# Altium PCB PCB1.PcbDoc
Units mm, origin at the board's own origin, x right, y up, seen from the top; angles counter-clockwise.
Board outline 84.71 x 55.88 mm, 2 copper layers (Top Layer, Bottom Layer); 58 components, 56 nets, 256 pads, 84 vias.
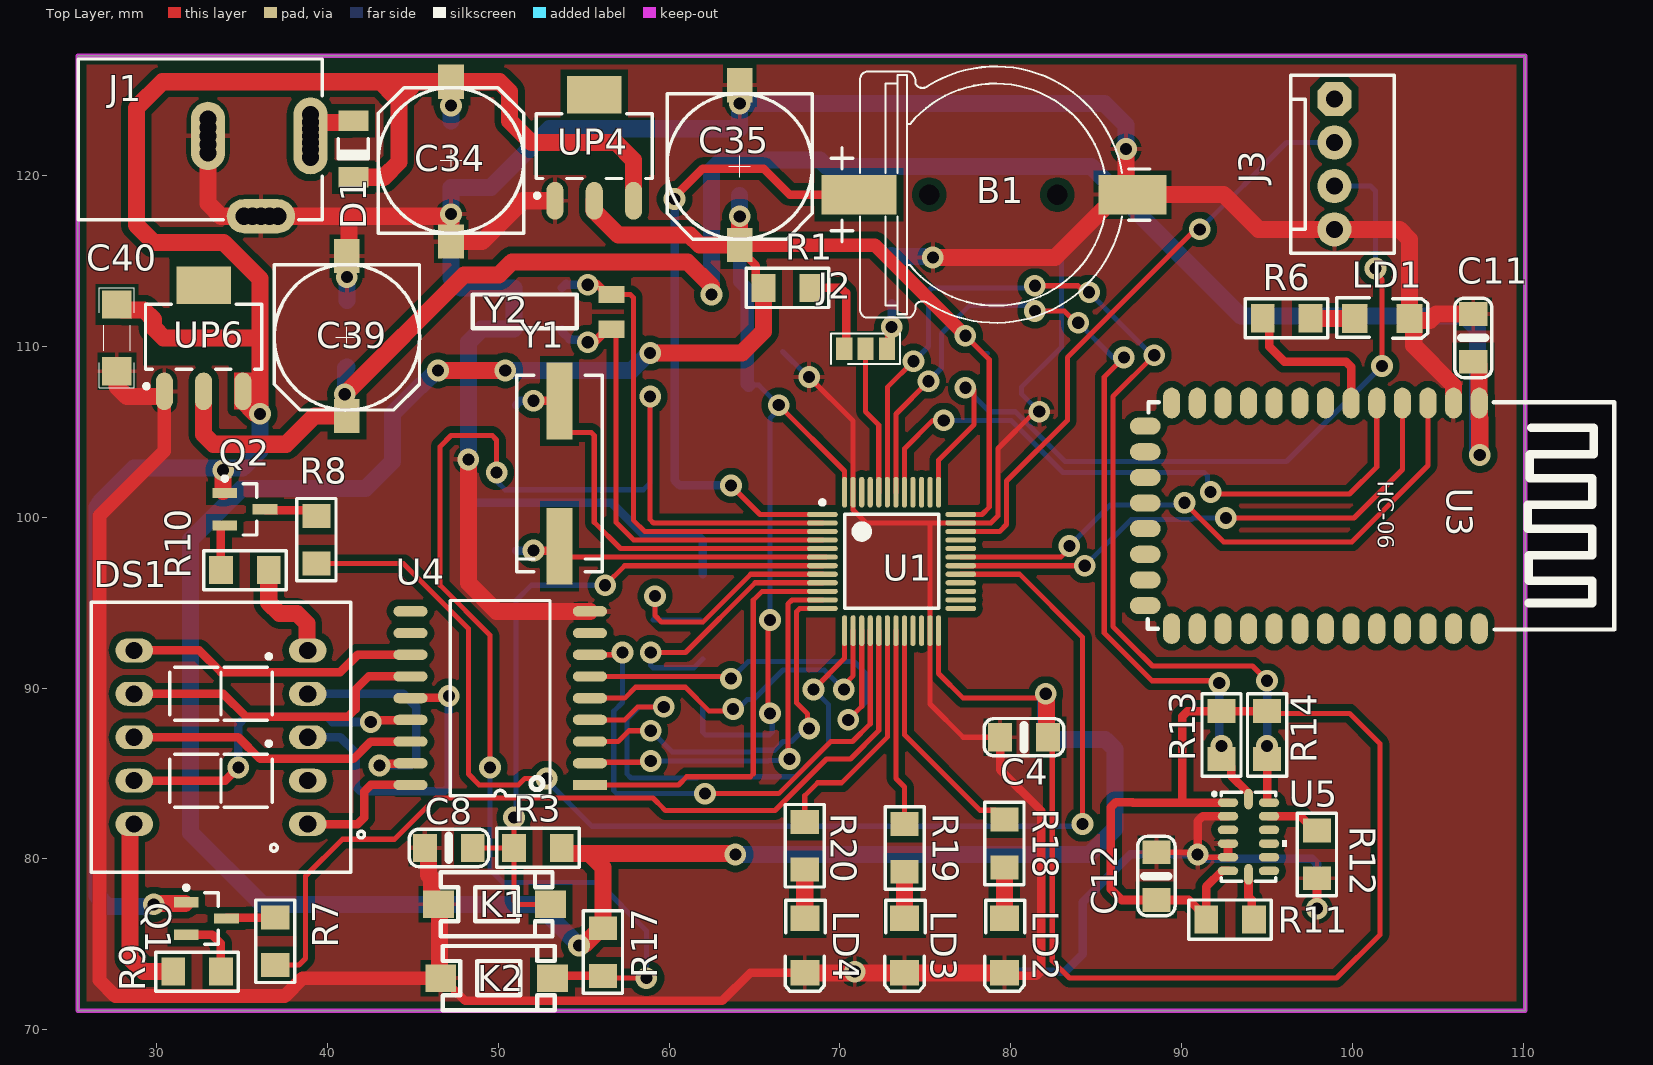
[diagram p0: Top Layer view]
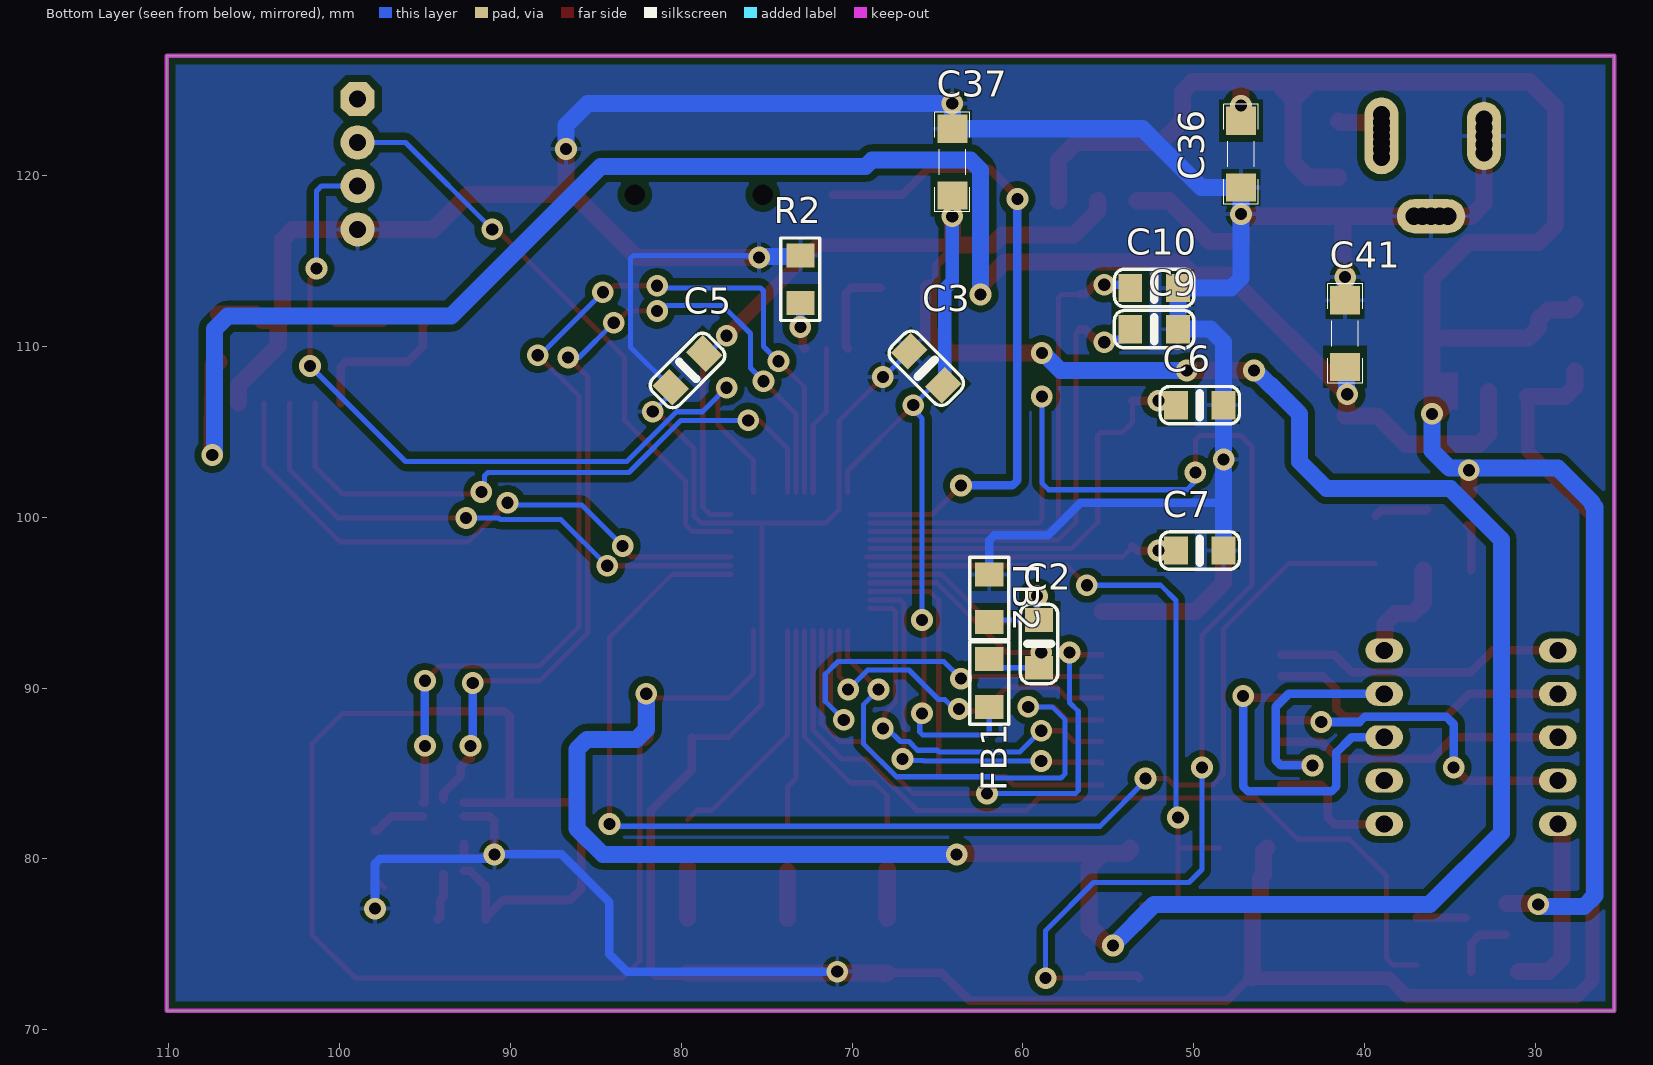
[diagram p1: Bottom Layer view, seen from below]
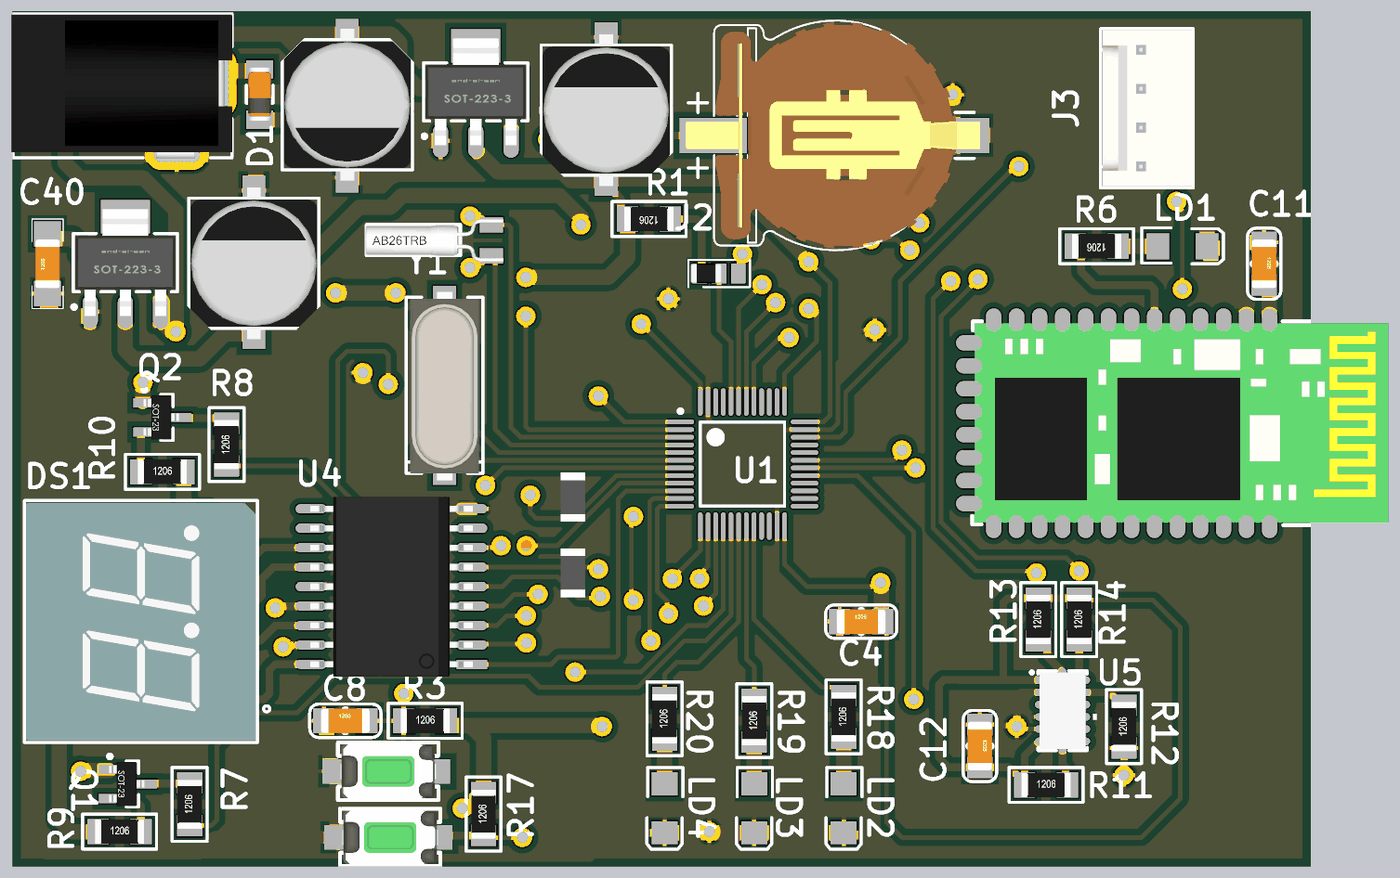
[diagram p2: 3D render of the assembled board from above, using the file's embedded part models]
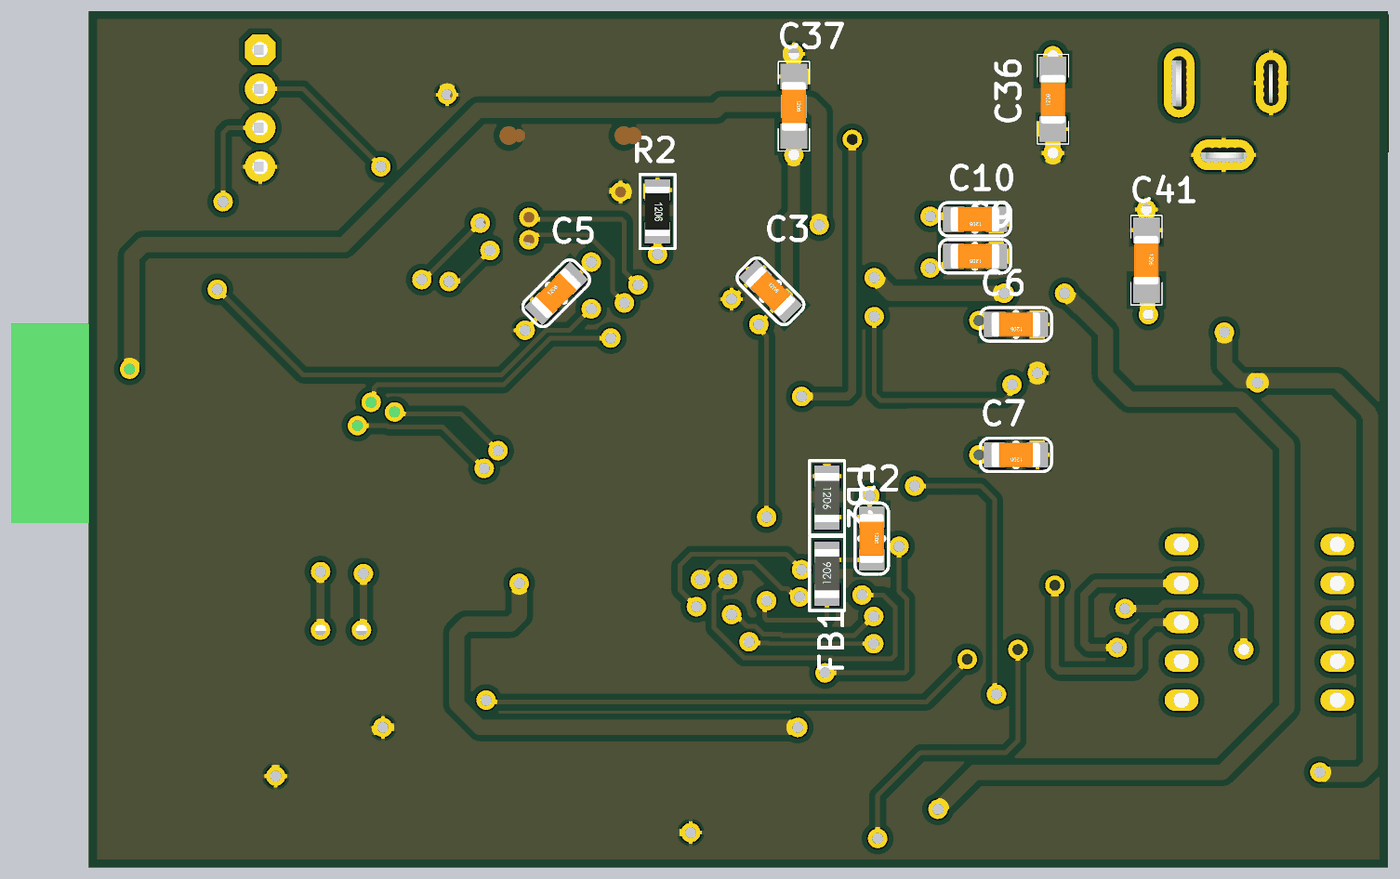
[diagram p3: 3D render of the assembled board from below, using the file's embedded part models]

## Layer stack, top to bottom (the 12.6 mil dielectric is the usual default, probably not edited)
Top Solder: solder mask 0.0102, Solder Resist, Dk 3.5
Top Layer: signal copper 0.0356
Dielectric 1: dielectric 0.32, FR-4, Dk 4.8
Bottom Layer: signal copper 0.0356
Bottom Solder: solder mask 0.0102, Solder Resist, Dk 3.5

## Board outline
25.4,71.12 110.109,71.12 110.109,127 25.4,127

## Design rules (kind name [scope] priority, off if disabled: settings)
Clearance [All] p1: gap=0.4 ignorepadtopadclearanceinfootprint=FALSE
PolygonConnect [All] p1: connectstyle=Relief reliefconductorwidth=0.254 reliefentries=4 polygonreliefangle="90 Angle" airgapwidth=0.254
RoutingVias [All] p1: holewidth=0.711 width=1.27 viastyle="Through Hole" minholewidth=0.711 minwidth=1.27 maxholewidth=0.711 maxwidth=1.27
SolderMaskExpansion [All] p1: expansion=0.102 istentingtop=FALSE
Width [All] p1: maxlimit=1 minlimit=0.254 preferedwidth=0.4
30 further rules are at their usual default settings.

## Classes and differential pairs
component class Segment: DS1 Q1 Q2 R7 R8 R9 R10 U4
component class PowerSupply: C34 C35 C36 C37 C39 C40 C41 D1 J1 UP4 UP6
component class Microcontroller: B1 C2 C3 C4 C5 C6 C7 C8 C9 C10 FB1 FB2 J2 J3 K1 K2 LD2 LD3 LD4 R1 R2 R3 R17 R18 R19 R20 U1 Y1 Y2
component class HC05: C11 LD1 R6 U3
component class ADXL345: C12 R11 R12 R13 R14 U5

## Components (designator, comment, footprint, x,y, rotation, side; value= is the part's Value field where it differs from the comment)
B1 "Battery" "Battery socket SMD" 79.121,118.872 r180 top
C2 "Capacitor SMD" "1206 Capacitor" 59.055,92.583 r270 bottom
C3 "Capacitor SMD" "1206 Capacitor" 65.659,108.712 r225 bottom
C4 "Capacitor SMD" "1206 Capacitor" 80.772,87.122 r0 top
C5 "Capacitor SMD" "1206 Capacitor" 79.629,108.585 r135 bottom
C6 "Capacitor SMD" "1206 Capacitor" 49.657,106.553 r0 bottom
C7 "Capacitor SMD" "1206 Capacitor" 49.657,98.044 r0 bottom
C8 "Capacitor SMD" "1206 Capacitor" 47.117,80.645 r0 top
C9 "Capacitor SMD" "1206 Capacitor" 52.324,110.998 r0 bottom
C10 "Capacitor SMD" "1206 Capacitor" 52.324,113.411 r0 bottom
C11 "Capacitor SMD" "1206 Capacitor" 107.061,110.49 r270 top
C12 "Capacitor SMD" "1206 Capacitor" 88.519,78.994 r270 top
C34 "" "CAPACITOR RADIAL SMT size F" 47.244,120.873 r90 top
C35 "" "CAPACITOR RADIAL SMT size F" 64.135,120.523 r270 top
C36 "0.1uF" CAPC4817X12N 47.244,121.24 r90 bottom
C37 "0.1uF" CAPC4817X12N 64.135,120.777 r270 bottom
C39 "" "CAPACITOR RADIAL SMT size F" 41.148,110.521 r270 top
C40 "0.1uF" CAPC4817X12N 27.686,110.49 r90 top
C41 "0.1uF" CAPC4817X12N 41.148,110.744 r270 bottom
D1 "1N4148" "Diode 1n4148 SMD" 41.529,123.188 r270 top
DS1 "7SEG_2DIGIT_CA" 7SEGX2_10_03INCH 33.782,87.122 r90 top
FB1 "Ferrit Bead" "1206 Ferrit Bead" 61.976,90.297 r90 bottom
FB2 "Ferrit Bead" "1206 Ferrit Bead" 61.976,95.25 r270 bottom
J1 "DC Power Jack" "DC Power Jack 1" 39.02,123.109 r0 top
J2 "Jumper Selector 3x1" "Jumper Selector 3x1 SMT" 71.501,109.855 r0 top
J3 "SWD" "CON WF_4" 98.933,120.65 r270 top
K1 "Push Kay" "Push Kay 4 KFC" 49.911,77.343 r270 top
K2 "Push Kay" "Push Kay 4 KFC" 50.038,73.025 r270 top
LD1 "SMD LED" "LED_1206 RED" 101.727,111.633 r0 top
LD2 "SMD LED" "LED_1206 RED" 79.629,74.93 r270 top
LD3 "SMD LED" "LED_1206 RED" 73.787,74.93 r270 top
LD4 "SMD LED" "LED_1206 RED" 67.945,74.93 r270 top
Q1 "BC807" SOT-23 32.925,76.515 r270 top
Q2 "BC807" SOT-23 35.179,100.457 r270 top
R1 "Resistor SMD" "1206 Resistor" 66.929,113.411 r180 top
R2 "Resistor SMD" "1206 Resistor" 73.025,113.919 r270 bottom
R3 "Resistor SMD" "1206 Resistor" 52.324,80.645 r0 top
R6 "Resistor SMD" "1206 Resistor" 96.139,111.633 r180 top
R7 "Resistor SMD" "1206 Resistor" 36.957,75.184 r90 top
R8 "Resistor SMD" "1206 Resistor" 39.37,98.679 r90 top
R9 "Resistor SMD" "1206 Resistor" 32.385,73.406 r0 top
R10 "Resistor SMD" "1206 Resistor" 35.179,96.901 r0 top
R11 "Resistor SMD" "1206 Resistor" 92.837,76.454 r0 top
R12 "Resistor SMD" "1206 Resistor" 97.917,80.264 r90 top
R13 "Resistor SMD" "1206 Resistor" 92.329,87.249 r90 top
R14 "Resistor SMD" "1206 Resistor" 94.996,87.249 r90 top
R17 "Resistor SMD" "1206 Resistor" 56.134,74.549 r90 top
R18 "Resistor SMD" "1206 Resistor" 79.629,80.899 r90 top
R19 "Resistor SMD" "1206 Resistor" 73.787,80.645 r90 top
R20 "Resistor SMD" "1206 Resistor" 67.945,80.772 r90 top
U1 "STM32F103C8T6" STM-LQFP48_N 73.025,97.409 r0 top
U3 "HC-05" BT_HC06 97.663,100.076 r270 top
U4 "ULN2803" SOIC18 50.122,89.408 r180 top
U5 "ADXL345" QFN80_14_5X3 93.91,81.299 r0 top
UP4 "LM1117IMP-3.3" SOT223_4 55.626,121.714 r90 top
UP6 "LM1117IMP-3.3" SOT223_4 32.766,110.562 r90 top
Y1 "Xtal" "Crystal SMD" 53.594,101.981 r90 top
Y2 "Xtal" "Xtal 32.782khz" 56.642,112.014 r180 top

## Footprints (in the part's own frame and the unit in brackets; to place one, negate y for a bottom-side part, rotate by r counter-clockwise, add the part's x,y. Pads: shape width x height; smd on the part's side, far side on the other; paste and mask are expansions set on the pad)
7SEGX2_10_03INCH [mm] "7SEG 2DIGIT 10pin Pitch: 2.54mm  0.3\", 15.5X15mm"
  oval 1.4x2.2 hole 1: 1(-5.08,-5.08) 3(0,-5.08) 4(2.54,-5.08) 5(5.08,-5.08) 6(5.08,5.08) 7(2.54,5.08) 8(0,5.08) 9(-2.54,5.08) 10(-5.08,5.08) ""(-2.54,-5.08)
  silkscreen extent -7.9,-8.4 7.9,7.6, body extent -7.75,-7.5 7.75,7.5, height 7.3
"1206 Capacitor" [mil]
  rect 55x65 smd: 1(-55,0) 2(55,0)
  silkscreen extent -92,-43 92,43, body extent -63,-31 63,31, height 39
"1206 Ferrit Bead" [mil]
  rect 55x65 smd: 1(-55,0) 2(55,0)
  silkscreen extent -95,-45 95,45, body extent -63,-31 63,31, height 26
"1206 Resistor" [mil]
  rect 55x65 smd: 1(-55,0) 2(55,0)
  silkscreen extent -95,-45 95,45, body extent -63,-31 63,31, height 24
"Battery socket SMD" [mm]
  rect 4.4x2.3 smd mask+0.05: 1(8,0)
  rect 4x2.3 smd mask+0.05: 2(-8,0)
  round 0.5 hole 1.2 unplated mask+0.05: ""(-3.6,0) ""(3.9,0)
  silkscreen extent -9.02,-7.5 9.63,7.5, body extent -9.4,-7.37 9.8,7.37, height 4.25
BT_HC06 [mm] "Bluetooth HC-06"
  oval 1.8x1 smd: 1(-6.6,9.75) 2(-6.6,8.25) 3(-6.6,6.75) 4(-6.6,5.25) 5(-6.6,3.75) 6(-6.6,2.25) 7(-6.6,0.75) 8(-6.6,-0.75) 9(-6.6,-2.25) 10(-6.6,-3.75) 11(-6.6,-5.25) 12(-6.6,-6.75) 13(-6.6,-8.25) 22(6.6,-8.25) 23(6.6,-6.75) 24(6.6,-5.25) 25(6.6,-3.75) 26(6.6,-2.25) 27(6.6,-0.75) 28(6.6,0.75) 29(6.6,2.25) 30(6.6,3.75) 31(6.6,5.25) 32(6.6,6.75) 33(6.6,8.25) 34(6.6,9.75)
  oval 1x1.8 smd: 14(-5.25,-9.8) 15(-3.75,-9.8) 16(-2.25,-9.8) 17(-0.75,-9.8) 18(0.75,-9.8) 19(2.25,-9.8) 20(3.75,-9.8) 21(5.25,-9.8)
  silkscreen extent -6.65,-9.65 6.65,17.65, body extent -6.5,-9.5 6.5,17.5, height 4.3
"CAPACITOR RADIAL SMT size F" [mm]
  rect 2x1.5 smd mask+0.051: 1(4.603,0) 2(-4.75,0)
  silkscreen extent -4.26,-4.26 4.26,4.25, body extent -4.95,-4.15 4.95,4.15, height 10.02
CAPC4817X12N [mm] "Chip Capacitor, 2-Leads, Body 4/80x1/70mm, IPC Medium Density-Design:Abbas Basereh"
  rect 1.65x1.75 smd: 1(-1.95,0) 2(1.95,0)
  silkscreen extent -2.92,-1.02 2.92,1.02, body extent -1.6,-0.8 1.6,0.8, height 1
"CON WF_4" [mm] "DS1070  WF, Cvilux CI31 pitch 2.54mm-Designer Abbas Basereh"
  oct 2x2 hole 1: 1(-3.81,0)
  round 2 hole 1: 2(-1.27,0) 3(1.27,0) 4(3.81,0)
  silkscreen extent -5.2,-2.55 5.2,3.5, body extent -5.08,-2.4 5.08,3.4, height 11.56
"Crystal SMD" [mm]
  rect 4.5x1.5 smd: 1(-3.683,0) 2(4.817,0)
  silkscreen extent -5.18,-2.5 6.32,2.5, body extent -5.64,-2.25 6.66,2.25, height 5.18
"DC Power Jack 1" [mm] "Power Adaptor Jack"
  round 1.5 hole 1: 1(0,-2.05) 1(0,-1.6) 1(0,-1.2) 1(0,-0.4) 1(0,0) 1(0,0.45) 2(-6,-1.8) 2(-6,0.2) 2(-6,-1.3) 2(-6,-0.3) 3(-3.9,-5.5) 3(-3.4,-5.5) 3(-2.4,-5.5) 3(-1.9,-5.5)
  oval 2x4.5 hole 1: 1(0,-0.8)
  oval 2x4 hole 1: 2(-6,-0.8)
  oval 4x2 hole 1: 3(-2.9,-5.5)
  silkscreen extent -13.59,-5.7 0.7,3.7, body extent -13.68,-5.74 0.72,3.66, height 11.05
"Diode 1n4148 SMD" [mm] "Mini MELF SOD-80"
  rect 1.2x1.75 smd: 1(0,0) 2(3.3,0)
  silkscreen extent 1.04,-0.88 2.22,0.87, body extent -0.13,-0.75 3.37,0.75, height 1.55
"Jumper Selector 3x1 SMT" [mm]
  rect 0.95x1.3 smd: 1(-1.25,0) 2(0,0) 3(1.25,0)
  silkscreen extent -2.01,-0.89 2.01,0.89, body extent -1.85,-0.63 0.18,0.64, height 0.6
"LED_1206 RED" [mm]
  rect 1.5x1.7 smd: 1(-1.6,0) 2(1.6,0)
  silkscreen extent -2.65,-1.15 2.67,1.2, body extent -1.6,-0.8 1.6,0.8, height 1.11
"Push Kay 4 KFC" [mm]
  rect 1.6x1.8 smd mask+0.04: 1(0,3.15) 2(0,-3.4)
  silkscreen extent -1.88,-3.27 1.87,3.28, body extent -1.75,-3.15 1.75,3.15, height 5.03
QFN80_14_5X3 [mm] "LGA_CC-14-1 ADXL345"
  oval 1.2x0.5 smd mask+0.075: 1(-1.2,2) 2(-1.2,1.2) 3(-1.2,0.4) 4(-1.2,-0.4) 5(-1.2,-1.2) 6(-1.2,-2) 8(1.2,-2) 9(1.2,-1.2) 10(1.2,-0.4) 11(1.2,0.4) 12(1.2,1.2) 13(1.2,2)
  oval 0.5x1.2 smd mask+0.075: 7(0,-2.2) 14(0,2.2)
  silkscreen extent -2.1,-2.6 2.24,2.6, body extent -1.5,-2.5 1.5,2.5, height 1.03
SOIC18 [mm]
  rect 2x0.6 smd: 1(-5.25,5.08)
  oval 2x0.6 smd: 2(-5.25,3.81) 3(-5.25,2.54) 4(-5.25,1.27) 5(-5.25,0) 6(-5.25,-1.27) 7(-5.25,-2.54) 8(-5.25,-3.81) 9(-5.25,-5.08) 10(5.25,-5.08) 11(5.25,-3.81) 12(5.25,-2.54) 13(5.25,-1.27) 14(5.25,0) 15(5.25,1.27) 16(5.25,2.54) 17(5.25,3.81) 18(5.25,5.08)
  silkscreen extent -2.91,-5.71 2.92,5.71, body extent -5.3,-5.87 5.3,5.88, height 2.67
SOT223_4 [mm] "SOT223, 4-Leads, Body 6.5x3.5mm, Pitch 2.30mm-Designer Abbas Basereh"
  oval 2.2x1 smd: 1(-3.2,2.3) 2(-3.2,0) 3(-3.2,-2.3)
  rect 2.2x3.2 smd: 4(3,0)
  Top Layer pour cut-out: -1.7,3.556 1.7,3.556 1.7,-3.556 -1.7,-3.556
  silkscreen extent -3.02,-3.4 1.9,3.47, body extent -3.5,-3.25 3.5,3.25, height 1.7
SOT-23 [mm]
  rect 0.6x1.45 smd: 1(-0.95,-1.175) 2(0.95,-1.175) 3(0,1.175)
  silkscreen extent -1.92,-1.3 1.5,0.7, body extent -1.45,-1.23 1.45,1.07, height 1
STM-LQFP48_N [mm] "QFP, 48-Leads, Body 7x7mm, Pitch 0.5mm, IPC Medium Density"
  oval 1.8x0.3 smd: 1(-4.05,2.75) 2(-4.05,2.25) 3(-4.05,1.75) 4(-4.05,1.25) 5(-4.05,0.75) 6(-4.05,0.25) 7(-4.05,-0.25) 8(-4.05,-0.75) 9(-4.05,-1.25) 10(-4.05,-1.75) 11(-4.05,-2.25) 12(-4.05,-2.75) 25(4.05,-2.75) 26(4.05,-2.25) 27(4.05,-1.75) 28(4.05,-1.25) 29(4.05,-0.75) 30(4.05,-0.25) 31(4.05,0.25) 32(4.05,0.75) 33(4.05,1.25) 34(4.05,1.75) 35(4.05,2.25) 36(4.05,2.75)
  oval 0.3x1.8 smd: 13(-2.75,-4.05) 14(-2.25,-4.05) 15(-1.75,-4.05) 16(-1.25,-4.05) 17(-0.75,-4.05) 18(-0.25,-4.05) 19(0.25,-4.05) 20(0.75,-4.05) 21(1.25,-4.05) 22(1.75,-4.05) 23(2.25,-4.05) 24(2.75,-4.05) 37(2.75,4.05) 38(2.25,4.05) 39(1.75,4.05) 40(1.25,4.05) 41(0.75,4.05) 42(0.25,4.05) 43(-0.25,4.05) 44(-0.75,4.05) 45(-1.25,4.05) 46(-1.75,4.05) 47(-2.25,4.05) 48(-2.75,4.05)
  silkscreen extent -4.17,-2.75 2.75,3.57, body extent -3.5,-3.5 3.5,3.5, height 1.6
"Xtal 32.782khz" [mil]
  rect 60x40 smd: 1(0,-40) 2(0,40)
  silkscreen extent 80,-40 320,38, body extent -31,-55 323,55, height 79

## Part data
B1: library part "Battry Backup"
C34 C35 C39: library part "Capacitor Tantalium"
C36 C37 C40 C41: library part "CAP SMD 1206", "CAP 1206"
D1: library part "1N4148 SMD", "General Semicoductor"
DS1: library part 7SEG_2DIGIT_CA_GRN_0.3INCH_10, "7SEGMENT, 2DIGIT, common cathode"
J1: "DC Power Jack. Center Pin 2.5mm. Diameter: 5.7mm"
J3: library part "Header 4 PIN Telecom.", "Header, 4-Pin Telecom."
LD1 LD2 LD3 LD4: library part "LED SMD"
U1: "ARM Cortex-M3 32-bit MCU, 64 KB Flash, 20 KB Internal RAM, 37 I/Os, 48-pin LQFP, -40 to 85 degC, Tray", I/Os (High Current)=37, Operating Frequency(F) (Processor speed) (MHz)=72, Supplier Part Number 1=497-6063-ND, Supply Voltage(Vcc) min (V)=2
U3: library part BT_HC-05_HDR, "Bluetooth Module, 2Mbps, 8Mb flash, 3.1~4.2V"
U5: library part ADXL345_LGA14, "Sensor, Accelerometer Digital, 3-Axis"
UP4 UP6: library part LM1117IMP-x.x, "x.x Volt, 800mA Low-Dropout Linear Regulator, 4-pin SOT-223"

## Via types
v1: diameter 1.27, hole 0.711, Top Layer to Bottom Layer, 84 vias

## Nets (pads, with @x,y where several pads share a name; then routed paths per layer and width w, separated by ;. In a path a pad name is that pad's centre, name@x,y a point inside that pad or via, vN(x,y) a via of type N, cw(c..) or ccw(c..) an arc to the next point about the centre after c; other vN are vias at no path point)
A: U1.10 U4.1 | length 24.2
  Top Layer w0.3: U4.1 60.56,84.328 61.036,84.805 64.752,84.805 64.928,84.981 64.928,95.133 65.454,95.659 U1.10
AGND: C2.1 FB2.2 U1.8 | length 16.7
  Top Layer w0.3: v1(59.182,95.377) 59.182,94.488 59.179,94.485 59.179,94.237 59.563,93.853 61.976,93.853 64.782,96.659 U1.8
  Bottom Layer w0.3: v1(59.182,95.377) 59.182,94.107 C2.1 61.849,93.98 FB2.2
B: U1.11 U4.2 | length 23
  Top Layer w0.3: U4.2 55.429,85.655 58.858,85.655 v1(58.928,85.725) ; v1(67.056,85.852) 66.968,85.94 66.968,94.926 67.201,95.159 U1.11
  Bottom Layer w0.3: v1(58.928,85.725) 65.778,85.725 65.821,85.768 66.972,85.768 v1(67.056,85.852)
BL_Key: U1.41 U3.5 | length 37.5
  Top Layer w0.3: U1.41 73.775,104.001 75.438,105.664 v1(76.073,105.664) ; v1(91.694,101.473) 91.821,101.346 99.822,101.346 101.413,102.937 U3.5
  Bottom Layer w0.3: v1(76.073,105.664) 80.01,105.664 83.058,102.616 91.313,102.616 91.508,102.421 91.508,101.659 v1(91.694,101.473)
BOOT0: J2.2 U1.44 | length 8.7
  Top Layer w0.3: J2.2 71.501,106.172 72.275,105.398 U1.44
C: U1.12 U4.3 | length 22.9
  Top Layer w0.3: U4.3 57.023,86.868 57.658,87.503 v1(58.928,87.503) ; v1(68.199,87.63) 68.113,87.716 68.113,88.478 67.468,89.123 67.468,94.483 67.644,94.659 U1.12
  Bottom Layer w0.3: v1(58.928,87.503) 58.944,87.503 60.183,86.264 64.924,86.264 65.02,86.36 66.167,86.36 66.675,86.868 67.175,86.868 67.937,87.63 v1(68.199,87.63)
CA1: R7.1 U1.17 | length 50.3
  Top Layer w0.3: R7.1 38.354,73.787 38.735,74.168 38.735,78.994 40.894,81.153 43.942,81.153 46.355,83.566 59.055,83.566 59.691,82.93 59.786,82.835 66.198,82.835 69.215,85.852 70.612,85.852 72.275,87.515 U1.17
CA2: R8.1 U1.29 | length 76.2
  Top Layer w0.3: R8.1 44.45,97.282 48.26,93.472 48.26,84.963 48.895,84.328 51.181,84.328 51.562,84.709 v1(52.832,84.709) ; U1.29 79.17,96.659 79.173,96.655 80.518,96.655 84.201,92.972 v1(84.201,82.042)
  Bottom Layer w0.3: v1(52.832,84.709) 52.832,84.582 55.499,81.915 84.074,81.915 v1(84.201,82.042)
COM1: DS1.10 R9.1 | length 10.9
  Top Layer w1: DS1.10 28.633,82.042 28.448,81.857 28.448,74.2 29.242,73.406 R9.1
COM2: DS1.5 R10.2 | length 6.2
  Top Layer w1: R10.2 36.576,94.996 37.211,94.361 38.227,94.361 38.813,93.775 38.813,92.251 DS1.5
D: U1.13 U4.4 | length 30.7
  Top Layer w0.3: U4.4 57.404,88.138 58.166,88.9 v1(59.69,88.9) ; v1(68.453,89.916) 70.275,91.738 U1.13
  Bottom Layer w0.3: v1(59.69,88.9) 58.293,88.9 57.531,88.138 57.531,84.981 57.772,84.74 61.63,84.74 61.695,84.805 67.406,84.805 69.342,86.741 69.342,89.027 v1(68.453,89.916)
E: U1.14 U4.5 | length 20.8
  Top Layer w0.3: U4.5 57.404,89.408 58.039,90.043 60.96,90.043 62.357,88.646 63.627,88.646 v1(63.754,88.773) ; v1(70.231,89.916) 70.231,90.178 70.775,90.722 U1.14
  Bottom Layer w0.3: v1(63.754,88.773) 64.016,88.773 64.572,89.329 64.945,89.329 66.675,91.059 69.088,91.059 v1(70.231,89.916)
F: U1.15 U4.6 | length 25.6
  Top Layer w0.3: U4.6 63.5,90.678 v1(63.627,90.551) ; v1(70.485,88.138) 71.275,88.928 71.275,91.897 U1.15
  Bottom Layer w0.3: v1(63.627,90.551) 64.635,91.559 70.817,91.559 71.567,90.809 71.567,89.22 v1(70.485,88.138)
G: U1.16 U4.7 | length 32.5
  Top Layer w0.3: U4.7 57.15,91.948 v1(57.277,92.075) ; v1(62.103,83.82) 66.417,83.82 69.465,86.868 70.739,86.868 71.775,87.904 71.775,91.293 U1.16
  Bottom Layer w0.3: v1(57.277,92.075) 57.277,89.154 56.769,88.646 56.769,83.996 56.945,83.82 v1(62.103,83.82)
GND: B1.2 C3.1 C4.1 C5.1 C6.1 C7.1 C8.1 C9.1 C10.1 C11.1 C12.1 C34.2 C35.2 C36.1 C37.1 C39.2 C40.1 C41.1 FB2.1 J1.2 J1.3 J3.4 K1.2 K2.2 LD1.2 LD2.2 LD3.2 LD4.2 R2.1 R12.1 U1.23 U1.35 U1.47 U3.2 U4.9 U5.2 U5.4 U5.5 UP4.1 UP6.1 | length 412.9
  Top Layer w0.3: v1(68.199,108.204) 70.775,105.628 U1.47 70.775,100.421 71.537,99.659 75.311,99.659 ; C4.1 77.216,87.122 75.275,89.063 U1.23 75.275,99.623 75.311,99.659 ; v1(81.661,106.172) 81.407,106.172 79.248,104.013 79.248,100.076 78.831,99.659 U1.35 75.311,99.659 ; C12.1 v1@90.932,80.391 ; v1(90.932,80.264) 91.097,80.099 U5.5 ; R12.1@97.369,78.318 R12.1
  Top Layer w0.5: K2.2 46.738,73.025 48.066,71.697 63.119,71.697 64.752,73.33 LD4.2 ; C4.1 79.375,85.217 81.788,82.804 81.788,73.445 81.495,73.152 79.807,73.152 LD2.2 ; v1(90.932,80.264) 90.932,82.206 91.225,82.499 U5.2 ; U5.5 U5.4 ; v1(97.917,77.089) R12.1
  Top Layer w0.8: UP6.1@30.466,107.061 30.466,103.872 26.67,100.076 26.67,72.898 27.588,71.98 37.523,71.98 38.568,73.025 K2.2
  Top Layer w1: C40.1 27.686,107.647 28.272,107.061 UP6.1@30.466,107.061 ; J1.2@33.02,123.309 33.02,122.309 33.02,121.309 33.02,118.364 33.775,117.609 35.12,117.609 35.62,117.609 36.12,117.609 36.62,117.609 37.12,117.609 41.148,117.609 ; v1(41.148,114.046) 41.148,114.859 41.275,114.986 41.275,117.482 41.148,117.609 ; C8.1 45.918,80.447 45.918,79.05 46.111,78.857 46.111,77.643 46.575,77.18 46.575,73.088 K2.2 ; v1(48.26,103.378) 48.26,96.139 49.911,94.488 U4.9 ; UP4.1 51.458,118.514 49.067,116.123 C34.2 v1(47.244,117.729) 47.171,117.729 47.051,117.609 41.148,117.609 ; LD4.2 LD4.2@68.148,73.33 ; LD4.2@68.199,73.279 LD4.2@68.148,73.33 ; v1(75.438,115.189) 82.588,115.189 86.271,118.872 B1.2 ; LD2.2 LD3.2 LD4.2@68.148,73.33 ; v1(86.741,121.539) 86.741,119.252 B1.2 ; U3.2 105.913,107.701 103.577,110.037 103.577,111.383 LD1.2@103.454,111.506 ; C11.1 104.902,111.887 104.521,111.506 LD1.2@103.454,111.506 ; B1.2 92.456,118.872 94.488,116.84 J3.4 102.741,116.84 103.327,116.254 LD1.2 LD1.2@103.454,111.506
  Bottom Layer w0.3: C3.1 68.016,108.331 68.072,108.331 v1(68.199,108.204) ; v1(75.438,115.189) 75.568,115.319 82.786,115.319 82.962,115.143 82.962,109.942 C5.1 80.617,107.216 v1(81.661,106.172)
  Bottom Layer w0.5: 48.26,101.219 48.641,100.838 56.642,100.838 58.547,98.933 61.683,98.933 61.976,98.64 FB2.1 ; v1(70.866,73.406) 83.185,73.406 84.201,74.422 84.201,77.47 86.995,80.264 v1(90.932,80.264) 91.186,80.01 97.624,80.01 97.917,79.717 v1(97.917,77.089)
  Bottom Layer w1: C41.1 v1(41.148,114.046) ; C7.1 48.26,101.219 C6.1 48.26,110.236 49.022,110.998 C9.1 C10.1 47.83,113.411 47.244,113.997 v1(47.244,117.729) C36.1 49.567,119.29 53.004,122.727 C37.1 v1(64.135,124.206) 85.471,124.206 86.741,122.936 v1(86.741,121.539) ; R2.1 73.1,115.241 75.386,115.241 v1(75.438,115.189)
LED1: R18.2 U1.20 | length 14
  Top Layer w0.3: U1.20 73.775,87.261 78.191,82.845 79.08,82.845 R18.2
LED2: R19.2 U1.19 | length 11.5
  Top Layer w0.3: U1.19 73.275,84.713 73.787,84.201 R19.2
LED3: R20.2 U1.18 | length 14
  Top Layer w0.3: R20.2 67.945,83.693 68.707,84.455 70.104,84.455 72.775,87.126 U1.18
NetB1_1: B1.1 U1.1 | length 38.2
  Top Layer w0.3: v1(63.627,101.854) 65.322,100.159 U1.1
  Top Layer w0.5: v1(60.325,118.618) 60.325,118.745 61.976,120.396 65.532,120.396 67.056,118.872 B1.1
  Bottom Layer w0.5: v1(60.325,118.618) 60.325,102.147 60.618,101.854 v1(63.627,101.854)
NetC2_2: C2.2 FB1.2 U1.9 | length 15.8
  Top Layer w0.3: v1(58.928,92.075) 60.96,92.075 65.044,96.159 U1.9
  Bottom Layer w0.3: v1(58.928,92.075) 58.928,91.313 C2.2 61.468,91.186 FB1.2
NetD1_1: D1.1 J1.1 | length 2.9
  Top Layer w1: J1.1@39.02,122.309 39.799,123.088 41.429,123.088 D1.1
NetDS1_1: DS1.1 U4.18 | length 7.8
  Top Layer w0.5: DS1.1 41.783,82.042 42.164,82.423 42.164,83.947 42.545,84.328 U4.18
NetDS1_3: DS1.3 U4.14 | length 18.5
  Top Layer w0.5: U4.14 44.891,89.427 47.009,89.427 v1(47.117,89.535)
  Bottom Layer w0.5: DS1.3 40.767,87.122 41.656,86.233 41.656,84.24 41.949,83.947 46.824,83.947 47.117,84.24 v1(47.117,89.535)
NetDS1_4: DS1.4 U4.17 | length 14
  Top Layer w0.5: v1(43.053,85.471) 43.161,85.579 44.853,85.579 U4.17
  Bottom Layer w0.5: DS1.4 44.45,89.662 45.212,88.9 45.212,85.764 44.919,85.471 v1(43.053,85.471)
NetDS1_6: DS1.6 U4.12 | length 17.1
  Top Layer w0.5: DS1.6 32.512,92.202 33.782,90.932 40.767,90.932 41.783,91.948 U4.12
NetDS1_7: DS1.7 U4.13 | length 18.4
  Top Layer w0.5: DS1.7 33.909,89.662 35.245,88.326 41.209,88.326 41.656,88.773 41.656,89.916 42.418,90.678 U4.13
NetDS1_8: DS1.8 U4.16 | length 17.1
  Top Layer w0.5: DS1.8 34.798,87.122 36.068,85.852 41.529,85.852 42.545,86.868 U4.16
NetDS1_9: DS1.9 U4.15 | length 19.6
  Top Layer w0.5: DS1.9 34.036,84.582 v1(34.798,85.344) ; v1(42.545,88.011) 42.653,88.119 44.853,88.119 U4.15
  Bottom Layer w0.5: v1(34.798,85.344) 34.798,87.884 35.24,88.326 39.992,88.326 40.307,88.011 v1(42.545,88.011) v1@42.398,87.864
NetJ2_1: J2.1 R1.1 | length 5.5
  Top Layer w0.5: R1.1 70.065,113.411 70.358,113.118 70.358,109.962 J2.1
NetJ2_3: J2.3 R2.2 | length 2.8
  Top Layer w0.5: J2.3 72.888,109.992 72.888,110.988 v1(73.025,111.125)
  Bottom Layer w0.5: v1(73.025,111.125) R2.2
NetLD1_1: LD1.1 R6.1 | length 2.6
  Top Layer w1: R6.1 LD1.1
NetLD2_1: LD2.1 R18.1 | length 3
  Top Layer w1: LD2.1 R18.1
NetLD3_1: LD3.1 R19.1 | length 2.7
  Top Layer w1: LD3.1 R19.1
NetLD4_1: LD4.1 R20.1 | length 2.8
  Top Layer w1: LD4.1 R20.1
NetQ1_2: Q1.2 R9.2 | length 3.9
  Top Layer w0.5: Q1.2 33.274,75.565 33.782,75.057 R9.2
NetQ1_3: Q1.3 R7.2 | length 2.9
  Top Layer w0.5: Q1.3 34.133,76.548 36.924,76.548 R7.2
NetQ2_2: Q2.2 R10.1 | length 2.8
  Top Layer w0.5: R10.1 33.782,99.457 33.832,99.507 Q2.2
NetQ2_3: Q2.3 R8.2 | length 3.2
  Top Layer w0.5: Q2.3 36.404,100.407 39.039,100.407 R8.2
NetR6_2: R6.2 U3.6 | length 9.2
  Top Layer w0.5: R6.2 95.123,111.252 95.123,109.982 96.012,109.093 99.62,109.093 99.913,108.8 U3.6
NetR11_2: R11.2 U5.7 | length 2.8
  Top Layer w0.5: U5.7 93.91,77.794 94.107,77.597 94.107,76.581 R11.2
NetR12_2: R12.2 U5.12 | length 3.2
  Top Layer w0.5: U5.12 96.952,82.499 97.79,81.661 R12.2
NRST: C8.2 K1.1 R3.1 U1.7 | length 41
  Top Layer w0.3: C8.2 R3.1 ; v1(50.927,82.423) R3.1 ; K1.1 51.103,77.343 50.927,77.519 R3.1 ; v1(56.261,96.012) 57.408,97.159 64.77,97.159 U1.7
  Bottom Layer w0.3: v1(50.927,82.423) 51.054,82.55 51.054,95.123 51.943,96.012 v1(56.261,96.012)
OSC32_IN: C10.2 U1.3 Y2.1 | length 29.1
  Top Layer w0.3: Y2.1 57.736,113.03 57.912,112.854 57.912,99.822 58.575,99.159 U1.3
  Top Layer w0.5: v1(55.245,113.6) 55.31,113.665 55.753,113.665 56.388,113.03 Y2.1
  Bottom Layer w0.5: C10.2 53.975,113.665 54.04,113.6 v1(55.245,113.6)
OSC32_OUT: C9.2 U1.4 Y2.2 | length 27.5
  Top Layer w0.3: Y2.2 56.896,110.744 56.896,99.695 57.932,98.659 U1.4
  Top Layer w0.5: v1(55.245,110.236) 55.626,110.236 56.388,110.998 Y2.2
  Bottom Layer w0.5: C9.2 53.721,110.871 54.17,110.422 54.297,110.422 54.336,110.383 55.098,110.383 v1(55.245,110.236)
OSC_IN: C6.2 U1.5 Y1.2 | length 25.3
  Top Layer w0.3: Y1.2 53.594,105.551 54.194,104.951 55.45,104.951 55.626,104.775 55.626,99.695 57.162,98.159 U1.5
  Top Layer w0.5: v1(52.07,106.807) 53.585,106.807 Y1.2
  Bottom Layer w0.5: C6.2 51.308,106.807 v1(52.07,106.807)
OSC_OUT: C7.2 U1.6 Y1.1 | length 18.5
  Top Layer w0.3: Y1.1 53.594,98.259 54.194,97.659 U1.6@69.194,97.659
  Top Layer w0.5: v1(52.07,98.044) 53.34,98.044 Y1.1
  Bottom Layer w0.5: C7.2 v1(52.07,98.044)
PushKey: K2.1 R17.1 U1.2 | length 82.9
  Top Layer w0.3: v1(49.53,85.344) 49.53,93.091 46.609,96.012 46.609,104.14 47.244,104.775 49.657,104.775 49.911,104.521 v1(49.911,102.616) ; R17.1 56.261,73.025 v1(58.674,73.025) ; v1(58.897,107.061) 58.897,99.853 59.091,99.659 U1.2
  Top Layer w0.5: K2.1 53.315,73.152 R17.1
  Bottom Layer w0.3: v1(49.53,85.344) 49.53,79.375 50.292,78.613 55.88,78.613 58.674,75.819 v1(58.674,73.025) ; v1(49.911,102.616) 49.908,102.613 49.908,102.111 50.419,101.6 58.498,101.6 58.897,101.999 v1(58.897,107.061)
RXD: U1.31 U3.3 | length 35.2
  Top Layer w0.3: U1.31 82.927,97.659 83.426,98.158 v1(83.426,98.315) ; v1(90.17,100.838) 92.456,98.552 99.949,98.552 104.413,103.016 U3.3
  Bottom Layer w0.3: v1(83.426,98.315) 85.821,100.711 90.043,100.711 v1(90.17,100.838)
SCL: R13.1 U1.42 U5.14 | length 55.2
  Top Layer w0.3: U1.42 73.275,106.041 v1(75.184,107.95) ; v1(81.407,112.068) 83.131,112.068 83.82,111.379 v1(83.947,111.379) ; v1(86.614,109.347) 85.471,108.204 85.471,93.218 88.265,90.424 92.075,90.424 v1(92.202,90.297)
  Top Layer w0.5: v1(92.329,86.614) R13.1 92.456,85.852 92.905,85.403 92.905,84.854 93.91,83.849 U5.14
  Bottom Layer w0.3: v1(75.184,107.95) 75.184,107.96 75.946,108.722 75.946,110.744 77.597,112.395 81.231,112.395 81.407,112.219 v1(81.407,112.068) ; v1(83.947,111.379) 85.979,109.347 v1(86.614,109.347)
  Bottom Layer w0.5: v1(92.202,90.297) 92.202,86.741 v1(92.329,86.614)
SDA: R14.1 U1.43 U5.13 | length 62.1
  Top Layer w0.3: U1.43 72.775,107.599 v1(74.302,109.126) ; v1(81.407,113.538) 83.939,113.538 84.32,113.157 v1(84.582,113.157) ; v1(88.392,109.474) 85.971,107.053 85.971,93.607 86.995,92.583 88.296,91.282 94.138,91.282 v1(94.996,90.424)
  Top Layer w0.5: v1(94.996,86.614) R14.1 94.996,83.299 U5.13
  Bottom Layer w0.3: v1(74.302,109.126) 74.319,109.126 75.184,109.991 75.184,113.235 75.36,113.411 81.28,113.411 v1(81.407,113.538) ; v1(84.582,113.157) 88.265,109.474 v1(88.392,109.474)
  Bottom Layer w0.5: v1(94.996,86.614) v1@94.996,90.297
SWC: J3.3 U1.37 | length 48.8
  Top Layer w0.3: U1.37 75.775,103.334 77.851,105.41 77.851,107.477 77.435,107.477 v1(77.343,107.569) ; v1(101.346,114.554) 101.346,114.292 101.727,113.911 v1(101.727,108.839)
  Bottom Layer w0.3: v1(77.343,107.569) 78.748,106.164 80.276,106.164 82.042,104.398 82.042,104.394 83.185,103.251 96.139,103.251 v1(101.727,108.839) ; J3.3 101.043,119.38 101.346,119.077 v1(101.346,114.554)
SWD: J3.2 U1.34 | length 34.9
  Top Layer w0.3: U1.34 79.347,99.159 79.756,99.568 79.756,102.108 83.312,105.664 83.312,109.351 90.801,116.84 v1(91.059,116.84)
  Bottom Layer w0.3: v1(91.059,116.84) 96.139,121.92 J3.2
TXD: U1.30 U3.4 | length 32.1
  Top Layer w0.3: U1.30 79.625,97.159 79.629,97.155 v1(84.328,97.155) ; v1(92.583,99.949) 100.076,99.949 102.913,102.786 U3.4
  Bottom Layer w0.3: v1(84.328,97.155) 87.026,99.853 90.578,99.853 90.674,99.949 v1(92.583,99.949)
VCC3.3: C3.2 C4.2 C5.2 C12.2 C35.1 C37.2 FB1.1 R1.2 R3.2 R11.1 R13.2 R14.2 R17.2 U1.24 U1.36 U1.48 U5.1 U5.6 UP4.2 | length 321.7
  Top Layer w0.3: v1(65.913,88.519) 65.786,88.646 65.786,93.853 v1(65.913,93.98) ; v1(66.421,106.553) 70.275,102.699 U1.48 ; U1.24 75.775,90.849 77.216,89.408 v1@81.534,89.408 ; U1.36 78.315,100.159 78.74,100.584 78.74,109.22 v1(77.343,110.617) ; C4.2 82.423,86.868 82.423,74.041 83.439,73.025 99.06,73.025 101.6,75.565 101.6,86.741 99.822,88.519 95.123,88.519 R14.2
  Top Layer w0.5: C35.1 64.135,115.67 65.083,114.721 65.083,113.86 R1.2 ; R11.1 R11.1@91.44,76.581 ; U5.6 92.36,79.299 91.44,78.379 R11.1@91.44,76.581 ; U5.1 90.056,83.299 ; R14.2 R13.2 90.336,88.646 90.043,88.353 90.043,83.312 90.056,83.299 ; 90.056,83.299 87.135,83.299 87.122,83.312 86.145,83.312 85.852,83.019 85.852,78.232 86.487,77.597 C12.2 90.424,77.597 R11.1@91.44,76.581
  Top Layer w0.8: C35.1 72.04,115.92 v1(77.343,110.617)
  Top Layer w1: v1(46.482,108.585) v1(50.419,108.585) ; R3.2 53.721,80.518 53.919,80.319 55.317,80.319 ; v1(54.737,74.93) 54.789,74.982 55.043,74.982 56.007,75.946 R17.2 56.134,79.502 55.317,80.319 ; UP4.2 55.626,117.914 57.04,116.5 61.219,116.5 61.8,115.92 C35.1 v1(64.135,117.602) ; v1(58.897,109.601) 64.262,109.601 65.532,110.871 R1.2 ; v1(63.881,80.264) 63.826,80.319 55.317,80.319 ; v1(82.042,89.662) 82.094,89.61 82.094,87.197 C4.2
  Bottom Layer w0.3: FB1.1 61.976,87.425 62.152,87.249 65.864,87.249 66.04,87.425 66.04,88.392 v1(65.913,88.519) ; C3.2 65.25,107.724 v1(66.421,106.553) 66.421,106.291 65.913,105.783 v1(65.913,93.98) ; v1(77.343,110.617) 78.387,109.573 C5.2
  Bottom Layer w0.8: v1(64.135,117.602) 64.135,113.792 64.581,113.346 64.581,107.814 C3.2
  Bottom Layer w1: v1(46.482,108.585) 46.409,108.585 45.52,107.696 45.466,107.696 43.815,106.045 43.815,103.251 42.234,101.67 34.995,101.67 32.004,98.679 32.004,81.534 36.195,77.343 52.324,77.343 v1(54.737,74.93) ; v1(50.419,108.585) 57.808,108.585 58.824,109.601 v1(58.897,109.601) ; v1(63.881,80.264) 84.582,80.264 86.106,81.788 86.106,86.409 85.52,86.995 82.628,86.995 82.042,87.581 v1(82.042,89.662) ; v1(64.135,117.602) C37.2
VCC3.3Bl: C11.2 C39.1 C41.2 U3.1 UP6.2 | length 110.1
  Top Layer w1: UP6.2 32.766,104.853 33.352,104.267 37.592,104.267 39.243,105.918 C39.1 41.073,105.993 41.073,107.136 v1(41.021,107.188) 48.006,114.173 50.038,114.173 50.8,114.935 61.087,114.935 62.484,113.538 v1(62.484,113.03) ; C11.2 107.188,109.093 107.387,108.895 107.387,107.102 107.413,107.076 U3.1 107.413,105.796 107.442,105.767 v1(107.442,103.632)
  Bottom Layer w1: v1(41.021,107.188) 41.073,107.24 41.073,108.719 C41.2 ; v1(62.484,113.03) 62.484,120.318 63.07,120.904 68.834,120.904 69.215,120.523 84.709,120.523 93.472,111.76 106.553,111.76 107.315,110.998 107.315,103.759 v1(107.442,103.632)
VCC5: C34.1 C36.2 C40.2 D1.2 Q1.1 Q2.1 UP4.3 UP6.3 | length 122.1
  Top Layer w1: C40.2 28.011,112.115 29.285,112.115 29.845,111.555 29.845,111.076 30.431,110.49 35.941,110.49 ; v1(29.845,77.343) 29.897,77.395 Q1.1@31.68,77.395 ; Q2.1@33.909,101.502 v1(33.909,102.743) ; UP6.3 35.066,106.762 35.731,106.097 36.016,106.097 v1(36.068,106.045) 36.068,113.95 33.94,116.078 29.845,116.078 28.829,117.094 28.829,123.952 30.353,125.476 44.196,125.476 ; D1.2 43.307,119.888 44.196,120.777 44.196,125.476 ; v1(47.244,124.079) C34.1 ; UP4.3 57.926,120.89 56.896,121.92 51.943,121.92 50.673,123.19 50.673,124.89 50.087,125.476 C34.1 ; 44.196,125.476 C34.1
  Bottom Layer w1: v1(29.845,77.343) 29.718,77.343 29.591,77.216 27.178,77.216 26.543,77.851 26.543,100.584 26.67,100.711 26.67,100.838 28.702,102.87 35.052,102.87 36.068,103.886 v1(36.068,106.045) ; C36.2 v1(47.244,124.079)
pads on no net: B1. DS1. J3.1 U1.21 U1.22 U1.25 U1.26 U1.27 U1.28 U1.32 U1.33 U1.38 U1.39 U1.40 U1.45 U1.46 U3.7 U3.8 U3.9 U3.10 U3.11 U3.12 U3.13 U3.14 U3.15 U3.16 U3.17 U3.18 U3.19 U3.20 U3.21 U3.22 U3.23 U3.24 U3.25 U3.26 U3.27 U3.28 U3.29 U3.30 U3.31 U3.32 U3.33 U3.34 U4.8 U4.10 U4.11 U5.3 U5.8 U5.9 U5.10 U5.11 UP4.4 UP6.4

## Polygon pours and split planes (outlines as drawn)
GND on Bottom Layer "GND_L02_P000" (solid, pour order 0): 110.109,127 25.4,127 25.4,71.12 110.109,71.12
GND on Top Layer "GND_L01_P001" (solid, pour order 1): 110.109,127 25.4,127 25.4,71.12 109.982,71.12 110.109,71.247

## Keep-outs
Keep-Out Layer:
  lines w0.254: 25.4,71.12 25.4,127 110.109,127 110.109,71.12 60.325,71.12 25.4,71.12

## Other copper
Top Layer:
  rectangle net VCC5: 34.544,106.299 36.576,108.458
  region net VCC5: 44.196,123.698 42.164,125.73 45.847,125.73 45.974,125.603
